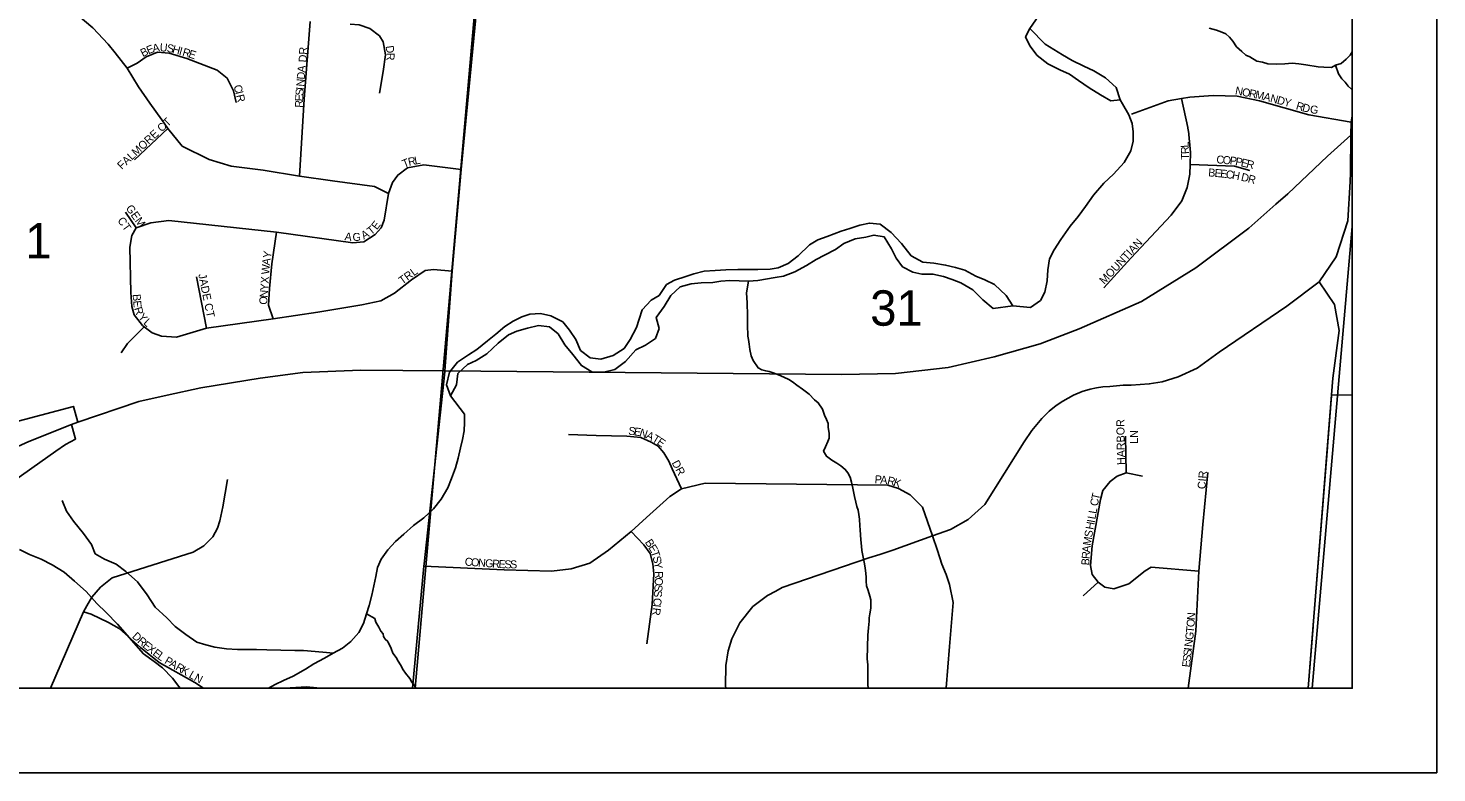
# Model space of a CAD drawing. Extents: x -209 to 4852, y 0 to 905.
# Drawn here: x 540.44 to 573.77, y 200.56 to 218.18 of the extents above; entities that cross this region are included whole.
import ezdxf

# ---------------------------------------------------------------- set-up
doc = ezdxf.new("R2010")
doc.units = 0
for name, color, linetype in [('Default', 7, 'Continuous'), ('GM_X_County_Road', 7, 'Continuous'), ('GM_X_County_ROW', 7, 'Continuous'), ('GM_X_Interstate_Location', 7, 'Continuous'), ('GM_X_Minor_Lake_Text', 7, 'Continuous'), ('GM_X_Minor_River', 7, 'Continuous'), ('GM_X_Rail_Line', 7, 'Continuous'), ('GM_X_Rail_Line_Text', 7, 'Continuous'), ('GM_X_Township_Road_Text', 7, 'Continuous'), ('GM_X_Township_Text', 7, 'Continuous'), ('GM_X_US_Location', 7, 'Continuous'), ('SH_Data', 7, 'Continuous')]:
    doc.layers.add(name, color=color, linetype=linetype)

msp = doc.modelspace()

# ---------------------------------------------------------------- linework, layer by layer
at = {"layer": 'Default'}
msp.add_lwpolyline([(571.768, 202.559), (571.768, 338.559), (435.768, 338.559), (435.768, 202.559)], close=True, dxfattribs=at)
at = {"layer": 'GM_X_County_Road'}
for points in [[(564.58, 219.962), (564.571, 219.893), (564.483, 219.659), (564.463, 219.416), (564.488, 219.15), (564.49, 218.861), (564.478, 218.656), (564.135, 218.168)], [(564.135, 218.168), (564.04, 217.972), (564.142, 217.757), (564.312, 217.533), (564.566, 217.331), (564.852, 217.188), (565.078, 217.085), (565.287, 216.936), (565.542, 216.764), (565.812, 216.599), (566.052, 216.458)], [(566.052, 216.458), (566.28, 216.484), (566.179, 216.774), (565.933, 217), (565.656, 217.165), (565.415, 217.276), (565.137, 217.411), (564.912, 217.544), (564.71, 217.67), (564.5, 217.796), (564.135, 218.168)], [(568.381, 218.177), (568.555, 218.127), (568.683, 218.085), (568.774, 218.045), (568.863, 217.967), (568.944, 217.866), (569.032, 217.735), (569.151, 217.625), (569.248, 217.539), (569.346, 217.499), (569.511, 217.396), (569.647, 217.37), (569.768, 217.329), (569.98, 217.323), (570.171, 217.334), (570.346, 217.345), (570.505, 217.333), (570.672, 217.306), (570.96, 217.261), (571.097, 217.25), (571.279, 217.246), (571.372, 217.304), (571.502, 217.339), (571.626, 217.442), (571.72, 217.539), (571.768, 217.62)], [(571.372, 217.304), (571.443, 217.097), (571.524, 216.981), (571.598, 216.896), (571.671, 216.802), (571.753, 216.732), (571.768, 216.718)], [(566.28, 216.484), (566.331, 216.384), (566.485, 216.122), (566.557, 215.923), (566.584, 215.725), (566.587, 215.504), (566.53, 215.277), (566.372, 214.999), (566.117, 214.722), (565.892, 214.506), (565.644, 214.222), (565.457, 213.96), (565.285, 213.72), (565.091, 213.495), (564.872, 213.18), (564.716, 212.932), (564.606, 212.722), (564.562, 212.456), (564.55, 212.198), (564.492, 211.933), (564.389, 211.737), (564.151, 211.567), (563.734, 211.605)], [(563.734, 211.605), (563.579, 211.852), (563.304, 212.108), (563.071, 212.219), (562.86, 212.307), (562.597, 212.449), (562.378, 212.514), (562.144, 212.572), (561.864, 212.615), (561.607, 212.643), (561.329, 212.793), (561.099, 213.079), (560.854, 213.342), (560.6, 213.537), (560.342, 213.565), (560.114, 213.517), (559.877, 213.438), (559.671, 213.373), (559.342, 213.25), (559.121, 213.171), (558.929, 213.053), (558.658, 212.792), (558.419, 212.607), (558.182, 212.505), (557.992, 212.478), (557.703, 212.469), (557.453, 212.466), (557.233, 212.463), (556.944, 212.461), (556.694, 212.443), (556.435, 212.425), (556.191, 212.361), (556, 212.304), (555.733, 212.218), (555.541, 212.108), (555.369, 211.853), (555.177, 211.743), (554.968, 211.511), (554.895, 211.292), (554.831, 211.095), (554.681, 210.809), (554.541, 210.599), (554.279, 210.429), (553.989, 210.344), (553.739, 210.379), (553.508, 210.551), (553.399, 210.812), (553.244, 211.028), (553.088, 211.228), (552.803, 211.371), (552.561, 211.429), (552.31, 211.411), (552.119, 211.346), (551.912, 211.244), (551.72, 211.118), (551.504, 210.94), (551.304, 210.777), (551.057, 210.576), (550.857, 210.451), (550.596, 210.274), (550.409, 210.034), (550.335, 209.739), (550.429, 209.478), (550.57, 209.742), (550.606, 210.007), (550.83, 210.216), (551.037, 210.311), (551.29, 210.473), (551.561, 210.726), (551.807, 210.919), (551.999, 211.006), (552.251, 211.078), (552.51, 211.141), (552.775, 211.113), (552.976, 210.942), (553.138, 210.688), (553.324, 210.456), (553.531, 210.193), (553.778, 210.044), (554.059, 210.038), (554.318, 210.102), (554.572, 210.294), (554.813, 210.563), (555.043, 210.673), (555.281, 210.836), (555.369, 211.07), (555.298, 211.33), (555.486, 211.592), (555.642, 211.848), (555.867, 212.056), (556.126, 212.127), (556.362, 212.153), (556.635, 212.163), (556.825, 212.189), (557.038, 212.208), (557.265, 212.196), (557.485, 212.192), (557.706, 212.21), (558.117, 212.278), (558.307, 212.312), (558.575, 212.414)], [(558.575, 212.414), (558.858, 212.56), (559.081, 212.7), (559.28, 212.803), (559.541, 212.942), (559.741, 213.083), (560.009, 213.192), (560.26, 213.232), (560.451, 213.282), (560.693, 213.239), (560.862, 212.954), (560.979, 212.732), (561.127, 212.531), (561.367, 212.405), (561.586, 212.355), (561.844, 212.357), (562.093, 212.299), (562.305, 212.234), (562.508, 212.154), (562.793, 211.989), (563.024, 211.749), (563.27, 211.546), (563.734, 211.605)], [(557.485, 212.192), (557.434, 211.911), (557.439, 211.797), (557.451, 211.682), (557.449, 211.591), (557.461, 211.469), (557.455, 211.241), (557.459, 211.074), (557.464, 210.975), (557.47, 210.891), (557.483, 210.807), (557.495, 210.7), (557.515, 210.571), (557.549, 210.425), (557.592, 210.31), (557.71, 210.14), (557.8, 210.092), (557.89, 210.067), (557.974, 210.05), (558.064, 210.025), (558.192, 209.976), (558.32, 209.919), (558.433, 209.863), (558.523, 209.808), (558.627, 209.729), (558.762, 209.635), (558.919, 209.517), (559.045, 209.384), (559.134, 209.314), (559.237, 209.159), (559.279, 209.021), (559.33, 208.921), (559.366, 208.822), (559.371, 208.738), (559.39, 208.585), (559.388, 208.479), (559.363, 208.396), (559.306, 208.268), (559.258, 208.17), (559.331, 208.047), (559.451, 207.953), (559.571, 207.881), (559.668, 207.818), (559.773, 207.739), (559.831, 207.654), (559.89, 207.554), (559.917, 207.432), (559.952, 207.294), (559.972, 207.179), (559.993, 207.095), (560.02, 206.965), (560.048, 206.858), (560.076, 206.774), (560.096, 206.667), (560.109, 206.56), (560.12, 206.4), (560.125, 206.309), (560.142, 206.073), (560.154, 205.921), (560.167, 205.821), (560.2, 205.623), (560.227, 205.501), (560.24, 205.401), (560.26, 205.279), (560.265, 205.18), (560.27, 205.097), (560.275, 204.982), (560.311, 204.875), (560.353, 204.737), (560.374, 204.653), (560.379, 204.554), (560.376, 204.455), (560.35, 204.319), (560.34, 204.228), (560.338, 204.145), (560.319, 203.993), (560.307, 203.818), (560.293, 203.256), (560.305, 203.111), (560.303, 203.013), (560.305, 202.815), (560.303, 202.731), (560.309, 202.648), (560.315, 202.559)], [(550.429, 209.478), (550.76, 209.046), (550.76, 208.848), (550.753, 208.651), (550.715, 208.447), (550.67, 208.251), (550.616, 208.003), (550.547, 207.777), (550.454, 207.522), (550.371, 207.305), (550.209, 207.037), (550.026, 206.801), (549.798, 206.589), (549.556, 206.407), (549.329, 206.203), (549.133, 206.028), (548.951, 205.837), (548.791, 205.615), (548.701, 205.42), (548.663, 205.201), (548.571, 204.764), (548.509, 204.516), (548.441, 204.32), (548.372, 204.095), (548.266, 203.878), (548.076, 203.665), (547.873, 203.505), (547.656, 203.392), (547.447, 203.27), (547.199, 203.135), (546.997, 203.013), (546.71, 202.849), (546.479, 202.743), (546.286, 202.651), (546.128, 202.559)], [(547.656, 203.392), (547.495, 203.407), (547.23, 203.427), (546.95, 203.455), (546.745, 203.452), (546.085, 203.465), (545.842, 203.477), (545.645, 203.473), (545.394, 203.478), (545.129, 203.491), (544.857, 203.534), (544.645, 203.584), (544.427, 203.649), (544.172, 203.829), (543.918, 204.024), (543.717, 204.226), (543.441, 204.482), (543.257, 204.767), (543.028, 205.076), (542.752, 205.325), (542.52, 205.497), (542.249, 205.616), (542.024, 205.742), (541.937, 205.964), (541.745, 206.219), (541.508, 206.513), (541.346, 206.751), (541.244, 207.004)], [(544.032, 202.559), (544.006, 202.605), (543.854, 202.801), (543.62, 203.045), (543.42, 203.196), (543.169, 203.373), (542.556, 204.079), (542.285, 204.355), (542.065, 204.568), (541.81, 204.851), (541.538, 205.096), (541.287, 205.31), (541.005, 205.48), (540.744, 205.611), (540.467, 205.728), (540.236, 205.843)], [(548.441, 204.32), (548.641, 204.208), (548.662, 204.124), (548.735, 204.008), (548.786, 203.908), (548.837, 203.846), (548.844, 203.785), (548.888, 203.723), (548.947, 203.668), (549.027, 203.499), (549.07, 203.392), (549.143, 203.291), (549.194, 203.199), (549.245, 203.114), (549.311, 202.998), (549.37, 202.913), (549.473, 202.789), (549.517, 202.704), (549.568, 202.634), (549.611, 202.559)]]:
    msp.add_lwpolyline(points, dxfattribs=at)
at = {"layer": 'GM_X_County_ROW'}
for points in [[(550.468, 212.426), (550.468, 212.427), (550.685, 214.831), (551.476, 223.02), (552.193, 231.821)], [(571.724, 214.753), (571.736, 215.645), (571.739, 215.951), (571.768, 216.105)], [(560.589, 205.725), (560.897, 205.823), (561.832, 206.163), (562.264, 206.314), (562.677, 206.556), (563.078, 206.906), (564.006, 208.386), (564.183, 208.656), (564.422, 208.938), (564.596, 209.112), (564.763, 209.248), (564.923, 209.354), (565.173, 209.493), (565.375, 209.579), (565.569, 209.635), (565.72, 209.671), (565.868, 209.688), (566.034, 209.701), (566.35, 209.728), (566.54, 209.734), (566.966, 209.759), (567.271, 209.811), (567.647, 209.927), (568.099, 210.132), (568.617, 210.508), (570.223, 211.601), (570.985, 212.176), (571.384, 212.768), (571.659, 213.619), (571.721, 214.552), (571.724, 214.753)], [(550.294, 210.048), (550.296, 210.071), (550.468, 212.426)], [(571.278, 209.483), (571.279, 209.501), (571.308, 209.898), (571.458, 211.023), (571.35, 211.641), (570.985, 212.176)], [(549.809, 205.504), (550.294, 210.048)], [(571.181, 208.276), (571.278, 209.48), (571.278, 209.483)], [(570.842, 204.052), (571.18, 208.267), (571.181, 208.276)], [(558.126, 204.86), (558.28, 204.942), (560.329, 205.642), (560.589, 205.725)], [(549.533, 202.559), (549.803, 205.45), (549.809, 205.504)], [(556.943, 202.559), (556.942, 202.614), (556.948, 203.1), (556.999, 203.442), (557.09, 203.73), (557.281, 204.105), (557.588, 204.492), (557.932, 204.757), (558.126, 204.86)], [(570.722, 202.559), (570.839, 204.021), (570.842, 204.052)], [(546.514, 202.559), (547.027, 202.593), (547.356, 202.559)]]:
    msp.add_lwpolyline(points, dxfattribs=at)
at = {"layer": 'GM_X_Minor_Lake_Text'}
msp.add_lwpolyline([(529.706, 202.559), (571.768, 202.559), (571.768, 262.071), (562.454, 262.602), (559.929, 262.758), (554.405, 263.075), (535.693, 268.436), (531.778, 225.399), (531.472, 222.006), (531.173, 218.724), (530.557, 211.945), (530.109, 207.025), (529.915, 204.912), (529.85, 204.169)], close=True, dxfattribs=at)
at = {"layer": 'GM_X_Minor_River'}
for points in [[(540.222, 202.559), (549.595, 202.559), (551.202, 220.877), (532.215, 227.465), (530.19, 207.083)], [(549.595, 202.559), (570.822, 202.559), (571.768, 213.482), (571.768, 220.234), (551.202, 220.877)], [(570.822, 202.559), (571.768, 202.559), (571.768, 213.482)]]:
    msp.add_lwpolyline(points, close=True, dxfattribs=at)
at = {"layer": 'GM_X_Rail_Line'}
for points in [[(541.615, 208.854), (541.511, 209.226), (538.144, 208.333), (537.948, 208.27)], [(538.461, 206.412), (538.704, 206.48), (541.09, 208.172), (541.326, 208.326), (541.559, 208.452), (541.461, 208.803)]]:
    msp.add_lwpolyline(points, dxfattribs=at)
at = {"layer": 'GM_X_Rail_Line_Text'}
for points in [[(569.963, 214.01), (570.243, 214.256), (571.185, 215.146), (571.736, 215.645), (571.768, 215.678)], [(537.096, 206.804), (538.203, 207.317), (539.077, 207.775), (540.455, 208.394), (541.461, 208.803), (541.615, 208.854), (543.055, 209.341), (543.731, 209.497), (544.522, 209.664), (545.926, 209.893), (546.935, 210.028), (548.309, 210.089), (550.296, 210.071), (559.683, 209.986), (560.96, 210.005), (562.204, 210.147), (563.298, 210.398), (564.382, 210.712), (565.308, 211.066), (566.779, 211.708), (568.07, 212.506), (569.318, 213.444), (569.963, 214.01)]]:
    msp.add_lwpolyline(points, dxfattribs=at)
at = {"layer": 'GM_X_Township_Text'}
for points in [[(541.456, 218.597), (541.626, 218.472), (541.968, 218.184), (542.334, 217.799), (542.5, 217.594), (542.779, 217.232), (543.05, 216.788), (543.316, 216.405), (543.6, 216.004), (543.742, 215.8), (544.085, 215.382), (544.723, 215.072), (545.242, 214.911), (546.001, 214.813), (546.859, 214.677), (547.643, 214.566), (548.63, 214.43), (548.965, 214.264)], [(547.11, 218.337), (546.97, 216.499), (546.859, 214.677)], [(548.055, 218.268), (548.27, 218.252), (548.525, 218.167), (548.751, 217.998), (548.836, 217.856), (548.893, 217.545), (548.836, 217.149), (548.751, 216.64)], [(542.779, 217.232), (543.02, 217.349), (543.229, 217.497), (543.501, 217.608), (543.779, 217.584), (544.192, 217.46), (544.914, 217.183), (545.149, 216.991), (545.297, 216.695), (545.358, 216.415)], [(571.739, 215.951), (570.739, 216.122), (569.575, 216.46), (569.046, 216.566), (568.474, 216.587), (567.923, 216.545), (567.729, 216.513), (567.415, 216.46), (566.547, 216.143)], [(567.888, 215.754), (567.881, 215.825), (567.729, 216.513)], [(543.742, 215.8), (542.954, 215.058)], [(565.891, 212.036), (566.526, 212.735), (567.479, 213.751), (567.733, 214.089), (567.86, 214.407), (567.923, 214.724), (567.933, 214.952), (567.944, 215.233), (567.889, 215.749), (567.888, 215.754)], [(550.685, 214.831), (549.797, 214.942), (549.414, 214.874), (549.185, 214.701), (549.06, 214.526), (548.965, 214.264), (548.866, 213.631), (548.79, 213.452), (548.65, 213.291), (548.38, 213.118), (548.124, 213.097), (546.316, 213.352), (543.771, 213.624), (543.345, 213.574), (542.994, 213.449)], [(567.933, 214.952), (568.982, 214.915), (569.342, 214.809)], [(542.994, 213.449), (542.743, 213.825)], [(550.468, 212.427), (550.031, 212.469), (549.832, 212.44), (549.506, 212.221), (549.105, 211.905), (548.785, 211.729), (548.332, 211.634), (547.293, 211.459), (546.239, 211.299), (544.662, 211.075), (543.947, 210.868), (543.595, 210.893), (543.37, 210.968), (543.184, 211.113), (543.144, 211.144), (542.944, 211.394), (542.893, 211.595), (542.868, 211.921), (542.843, 212.998), (542.893, 213.274), (542.994, 213.449)], [(546.239, 211.299), (546.127, 211.62), (546.152, 212.02), (546.202, 212.597), (546.316, 213.352)], [(544.662, 211.075), (544.423, 212.296)], [(542.643, 210.492), (542.793, 210.718), (543.184, 211.113)], [(555.899, 207.281), (555.675, 207.75), (555.594, 207.933), (555.48, 208.132), (555.343, 208.285), (555.18, 208.383), (554.935, 208.494), (554.602, 208.52), (553.875, 208.543), (553.22, 208.566)], [(566.416, 207.658), (566.402, 208.521)], [(568.134, 205.333), (567.013, 205.421), (566.864, 205.34), (566.478, 205.029), (566.123, 204.913), (565.911, 204.955), (565.756, 205.071), (565.615, 205.251), (565.572, 205.463), (565.615, 205.929), (565.809, 207.023), (565.869, 207.241), (566.038, 207.453), (566.208, 207.58), (566.416, 207.658), (566.801, 207.58)], [(568.348, 207.665), (568.231, 206.437), (568.134, 205.333), (568.065, 203.912), (567.885, 202.559)], [(541.828, 204.507), (541.948, 204.716), (542.15, 204.95), (542.426, 205.174), (544.345, 205.782), (544.595, 205.928), (544.701, 206.029), (544.811, 206.139), (544.915, 206.347), (544.972, 206.524), (545.045, 206.852), (545.157, 207.499)], [(549.803, 205.45), (551.703, 205.362), (552.819, 205.332), (553.288, 205.386), (553.727, 205.516), (554.167, 205.825), (554.707, 206.27), (555.069, 206.597), (555.619, 207.099), (555.899, 207.281), (556.458, 207.415), (560.779, 207.361), (561.032, 207.285), (561.305, 207.134), (561.598, 206.844), (561.832, 206.163), (561.951, 205.816), (562.059, 205.494), (562.156, 205.252), (562.236, 205.016), (562.327, 204.589), (562.235, 203.546), (562.16, 202.571), (562.16, 202.559)], [(554.707, 206.27), (555.004, 205.949), (555.158, 205.748), (555.218, 205.504), (555.241, 205.267), (555.2, 204.542), (555.08, 203.608)], [(565.403, 204.743), (565.756, 205.071)], [(540.965, 202.559), (541.747, 204.365), (541.828, 204.507)], [(544.584, 202.559), (544.385, 202.695), (543.54, 203.172), (543.097, 203.527), (542.592, 203.976), (542.34, 204.113), (541.931, 204.31), (541.747, 204.365)]]:
    msp.add_lwpolyline(points, dxfattribs=at)
at = {"layer": 'GM_X_US_Location'}
msp.add_lwpolyline([(570.722, 202.559), (571.768, 202.559), (571.768, 209.491), (571.28, 209.501)], close=True, dxfattribs=at)
msp.add_lwpolyline([(570.722, 202.559), (571.768, 202.559), (571.768, 209.491), (571.28, 209.501)], close=True, dxfattribs=at)
at = {"layer": 'SH_Data'}
for p, q in [((573.768, 340.559), (573.768, 200.559)), ((571.768, 338.559), (571.768, 202.559)), ((435.768, 202.559), (571.768, 202.559)), ((433.768, 200.559), (573.768, 200.559))]:
    msp.add_line(p, q, dxfattribs=at)

# ---------------------------------------------------------------- texts
at = {"layer": 'GM_X_Interstate_Location'}
for s, height, rotation, p in [('B', 0.189, 27.7925, (543.154, 217.488)), ('E', 0.189, 22.0398, (543.282, 217.556)), ('A', 0.189, 10.6626, (543.396, 217.603)), ('U', 0.189, 355.1638, (543.546, 217.633)), ('S', 0.189, 350.0031, (543.708, 217.619)), ('H', 0.189, 344.7602, (543.835, 217.597)), ('I', 0.189, 344.2887, (543.995, 217.554)), ('R', 0.189, 343.7009, (544.075, 217.531)), ('E', 0.189, 342.0316, (544.217, 217.49)), ('DR', 0.1894, 86.9769, (547.026, 217.363)), ('D', 0.189, 278.3341, (548.896, 217.751)), ('R', 0.189, 268.7615, (548.92, 217.594)), ('D', 0.189, 85.2291, (546.981, 216.955)), ('A', 0.189, 85.2514, (546.994, 217.121)), ('C', 0.189, 286.4992, (545.295, 216.807)), ('I', 0.189, 283.8136, (545.337, 216.665)), ('S', 0.189, 85.4043, (546.949, 216.573)), ('I', 0.189, 85.2291, (546.96, 216.706)), ('N', 0.189, 85.2514, (546.967, 216.789)), ('N', 0.189, 348.9601, (568.985, 216.612)), ('O', 0.189, 348.9648, (569.148, 216.58)), ('R', 0.189, 348.9567, (569.312, 216.549)), ('M', 0.189, 347.647, (569.458, 216.52)), ('A', 0.189, 345.1685, (569.651, 216.478)), ('R', 0.189, 283.4296, (545.356, 216.585)), ('R', 0.189, 89.7085, (546.942, 216.294)), ('E', 0.189, 87.2945, (546.943, 216.442)), ('N', 0.189, 345.0784, (569.812, 216.435)), ('D', 0.189, 345.0573, (569.973, 216.392)), ('Y', 0.189, 345.0825, (570.134, 216.349)), ('R', 0.189, 343.5008, (570.422, 216.261)), ('D', 0.189, 344.61, (570.569, 216.218)), ('G', 0.189, 352.8249, (570.759, 216.168)), ('FALMORE CT', 0.1894, 43.1534, (542.654, 214.82)), ('L', 0.189, 93.5349, (567.901, 215.355)), ('R', 0.189, 92.3952, (567.907, 215.201)), ('T', 0.189, 22.0398, (549.333, 214.869)), ('R', 0.189, 11.7148, (549.448, 214.916)), ('L', 0.189, 10.3293, (549.593, 214.947)), ('T', 0.189, 90.6284, (567.909, 215.061)), ('C', 0.189, 355.4784, (568.547, 214.98)), ('O', 0.189, 355.4999, (568.697, 214.968)), ('P', 0.189, 353.512, (568.861, 214.955)), ('P', 0.189, 348.1704, (568.989, 214.94)), ('E', 0.189, 346.5733, (569.118, 214.913)), ('R', 0.189, 346.4939, (569.248, 214.883)), ('B', 0.189, 355.2101, (568.354, 214.672)), ('E', 0.189, 355.132, (568.503, 214.659)), ('E', 0.189, 354.0067, (568.635, 214.648)), ('C', 0.189, 351.7154, (568.766, 214.634)), ('H', 0.189, 349.4059, (568.912, 214.613)), ('D', 0.189, 346.2288, (569.122, 214.572)), ('R', 0.189, 345.6162, (569.283, 214.532)), ('GEM', 0.1894, 305.7546, (542.74, 213.915)), ('CT', 0.1894, 305.5436, (542.542, 213.625)), ('A', 0.189, 352.3924, (547.918, 213.162)), ('G', 0.189, 2.168, (548.118, 213.139)), ('A', 0.189, 29.9952, (548.38, 213.172)), ('T', 0.189, 38.8471, (548.551, 213.274)), ('E', 0.189, 52.4875, (548.689, 213.393)), ('MOUNTIAN', 0.1894, 47.122, (565.902, 212.102)), ('A', 0.189, 82.8777, (546.157, 212.558)), ('Y', 0.189, 81.5114, (546.178, 212.722)), ('JADE CT', 0.1894, 281.5114, (544.463, 212.351)), ('W', 0.189, 85.8269, (546.142, 212.345)), ('TRL', 0.1894, 36.028, (549.291, 212.104)), ('Y', 0.189, 86.0407, (546.115, 211.962)), ('X', 0.189, 86.0407, (546.127, 212.129)), ('B', 0.189, 273.9853, (542.911, 211.879)), ('E', 0.189, 275.2596, (542.922, 211.725)), ('O', 0.189, 86.0405, (546.092, 211.63)), ('N', 0.189, 86.0187, (546.104, 211.796)), ('R', 0.189, 288.2013, (542.944, 211.547)), ('Y', 0.189, 310.0591, (543.028, 211.337)), ('L', 0.189, 316.7368, (543.151, 211.192)), ('S', 0.189, 352.2176, (554.631, 208.563)), ('E', 0.189, 352.2176, (554.763, 208.545)), ('N', 0.189, 342.0696, (554.886, 208.529)), ('HARBOR', 0.1894, 90.9872, (566.392, 207.843)), ('LN', 0.1894, 90, (566.698, 208.344)), ('A', 0.189, 334.921, (555.039, 208.48)), ('T', 0.189, 329.7908, (555.186, 208.411)), ('E', 0.189, 325.0214, (555.298, 208.346)), ('DR', 0.1894, 297.8914, (555.659, 207.894)), ('CIR', 0.1894, 85.0241, (568.292, 207.264)), ('P', 0.189, 355.8716, (560.462, 207.413)), ('A', 0.189, 355.894, (560.595, 207.403)), ('R', 0.189, 346.27, (560.753, 207.393)), ('K', 0.189, 340.777, (560.894, 207.358)), ('C', 0.189, 79.2759, (565.745, 206.858)), ('T', 0.189, 76.4012, (565.772, 207.003)), ('L', 0.189, 79.6707, (565.688, 206.547)), ('L', 0.189, 79.6843, (565.712, 206.678)), ('H', 0.189, 79.6717, (565.643, 206.301)), ('I', 0.189, 79.6825, (565.673, 206.465)), ('B', 0.189, 302.2216, (555.024, 206.015)), ('M', 0.189, 80.7054, (565.578, 205.924)), ('S', 0.189, 79.6707, (565.61, 206.12)), ('C', 0.189, 356.0147, (550.764, 205.463)), ('E', 0.189, 302.2195, (555.104, 205.888)), ('T', 0.189, 289.4719, (555.17, 205.785)), ('S', 0.189, 282.3066, (555.212, 205.666)), ('R', 0.189, 85.8192, (565.553, 205.613)), ('A', 0.189, 85.0331, (565.564, 205.762)), ('O', 0.189, 356.0065, (550.913, 205.452)), ('N', 0.189, 355.9969, (551.08, 205.441)), ('G', 0.189, 356.0182, (551.246, 205.429)), ('R', 0.189, 356.0147, (551.412, 205.418)), ('E', 0.189, 356.5313, (551.564, 205.407)), ('S', 0.189, 359.0279, (551.706, 205.399)), ('S', 0.189, 359.9707, (551.842, 205.396)), ('Y', 0.189, 278.467, (555.24, 205.539)), ('R', 0.189, 271.3842, (555.269, 205.33)), ('B', 0.189, 85.8434, (565.542, 205.463)), ('S', 0.189, 265.9806, (555.263, 205.018)), ('O', 0.189, 266.8287, (555.273, 205.184)), ('C', 0.189, 265.5994, (555.241, 204.703)), ('S', 0.189, 265.9806, (555.254, 204.885)), ('R', 0.189, 263.2334, (555.222, 204.473)), ('I', 0.189, 264.3068, (555.23, 204.554)), ('N', 0.189, 85.759, (568.044, 204.167)), ('T', 0.189, 84.7574, (568.019, 203.864)), ('O', 0.189, 85.714, (568.032, 204)), ('D', 0.189, 317.2264, (542.885, 203.77)), ('R', 0.189, 318.0276, (543.01, 203.655)), ('E', 0.189, 321.3359, (543.13, 203.546)), ('N', 0.189, 83.4466, (567.981, 203.528)), ('G', 0.189, 83.4914, (568, 203.694)), ('X', 0.189, 322.1995, (543.237, 203.461)), ('E', 0.189, 322.2392, (543.369, 203.359)), ('L', 0.189, 324.5634, (543.481, 203.272)), ('P', 0.189, 329.7069, (543.648, 203.159)), ('S', 0.189, 83.4465, (567.941, 203.181)), ('S', 0.189, 83.4274, (567.956, 203.313)), ('I', 0.189, 83.408, (567.971, 203.445)), ('A', 0.189, 329.9103, (543.763, 203.091)), ('R', 0.189, 329.9358, (543.908, 203.007)), ('K', 0.189, 329.8946, (544.037, 202.932)), ('L', 0.189, 329.9396, (544.225, 202.823)), ('E', 0.189, 83.4274, (567.926, 203.048)), ('N', 0.189, 332.1507, (544.347, 202.753))]:
    msp.add_text(s, height=height, rotation=rotation, dxfattribs=at).set_placement(p)
at = {"layer": 'GM_X_Township_Road_Text'}
for s, height, p in [('1', 0.837, (540.37, 212.729)), ('31', 0.8371, (560.361, 211.137))]:
    msp.add_text(s, height=height, rotation=0, dxfattribs=at).set_placement(p)

doc.saveas('drawing.dxf')
